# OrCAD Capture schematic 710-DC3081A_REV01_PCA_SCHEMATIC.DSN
size Custom; rev: 01; note: DEMO CIRCUIT 3081A; note: SINGLE SWITCH TRANSMITTER FOR LTC4126
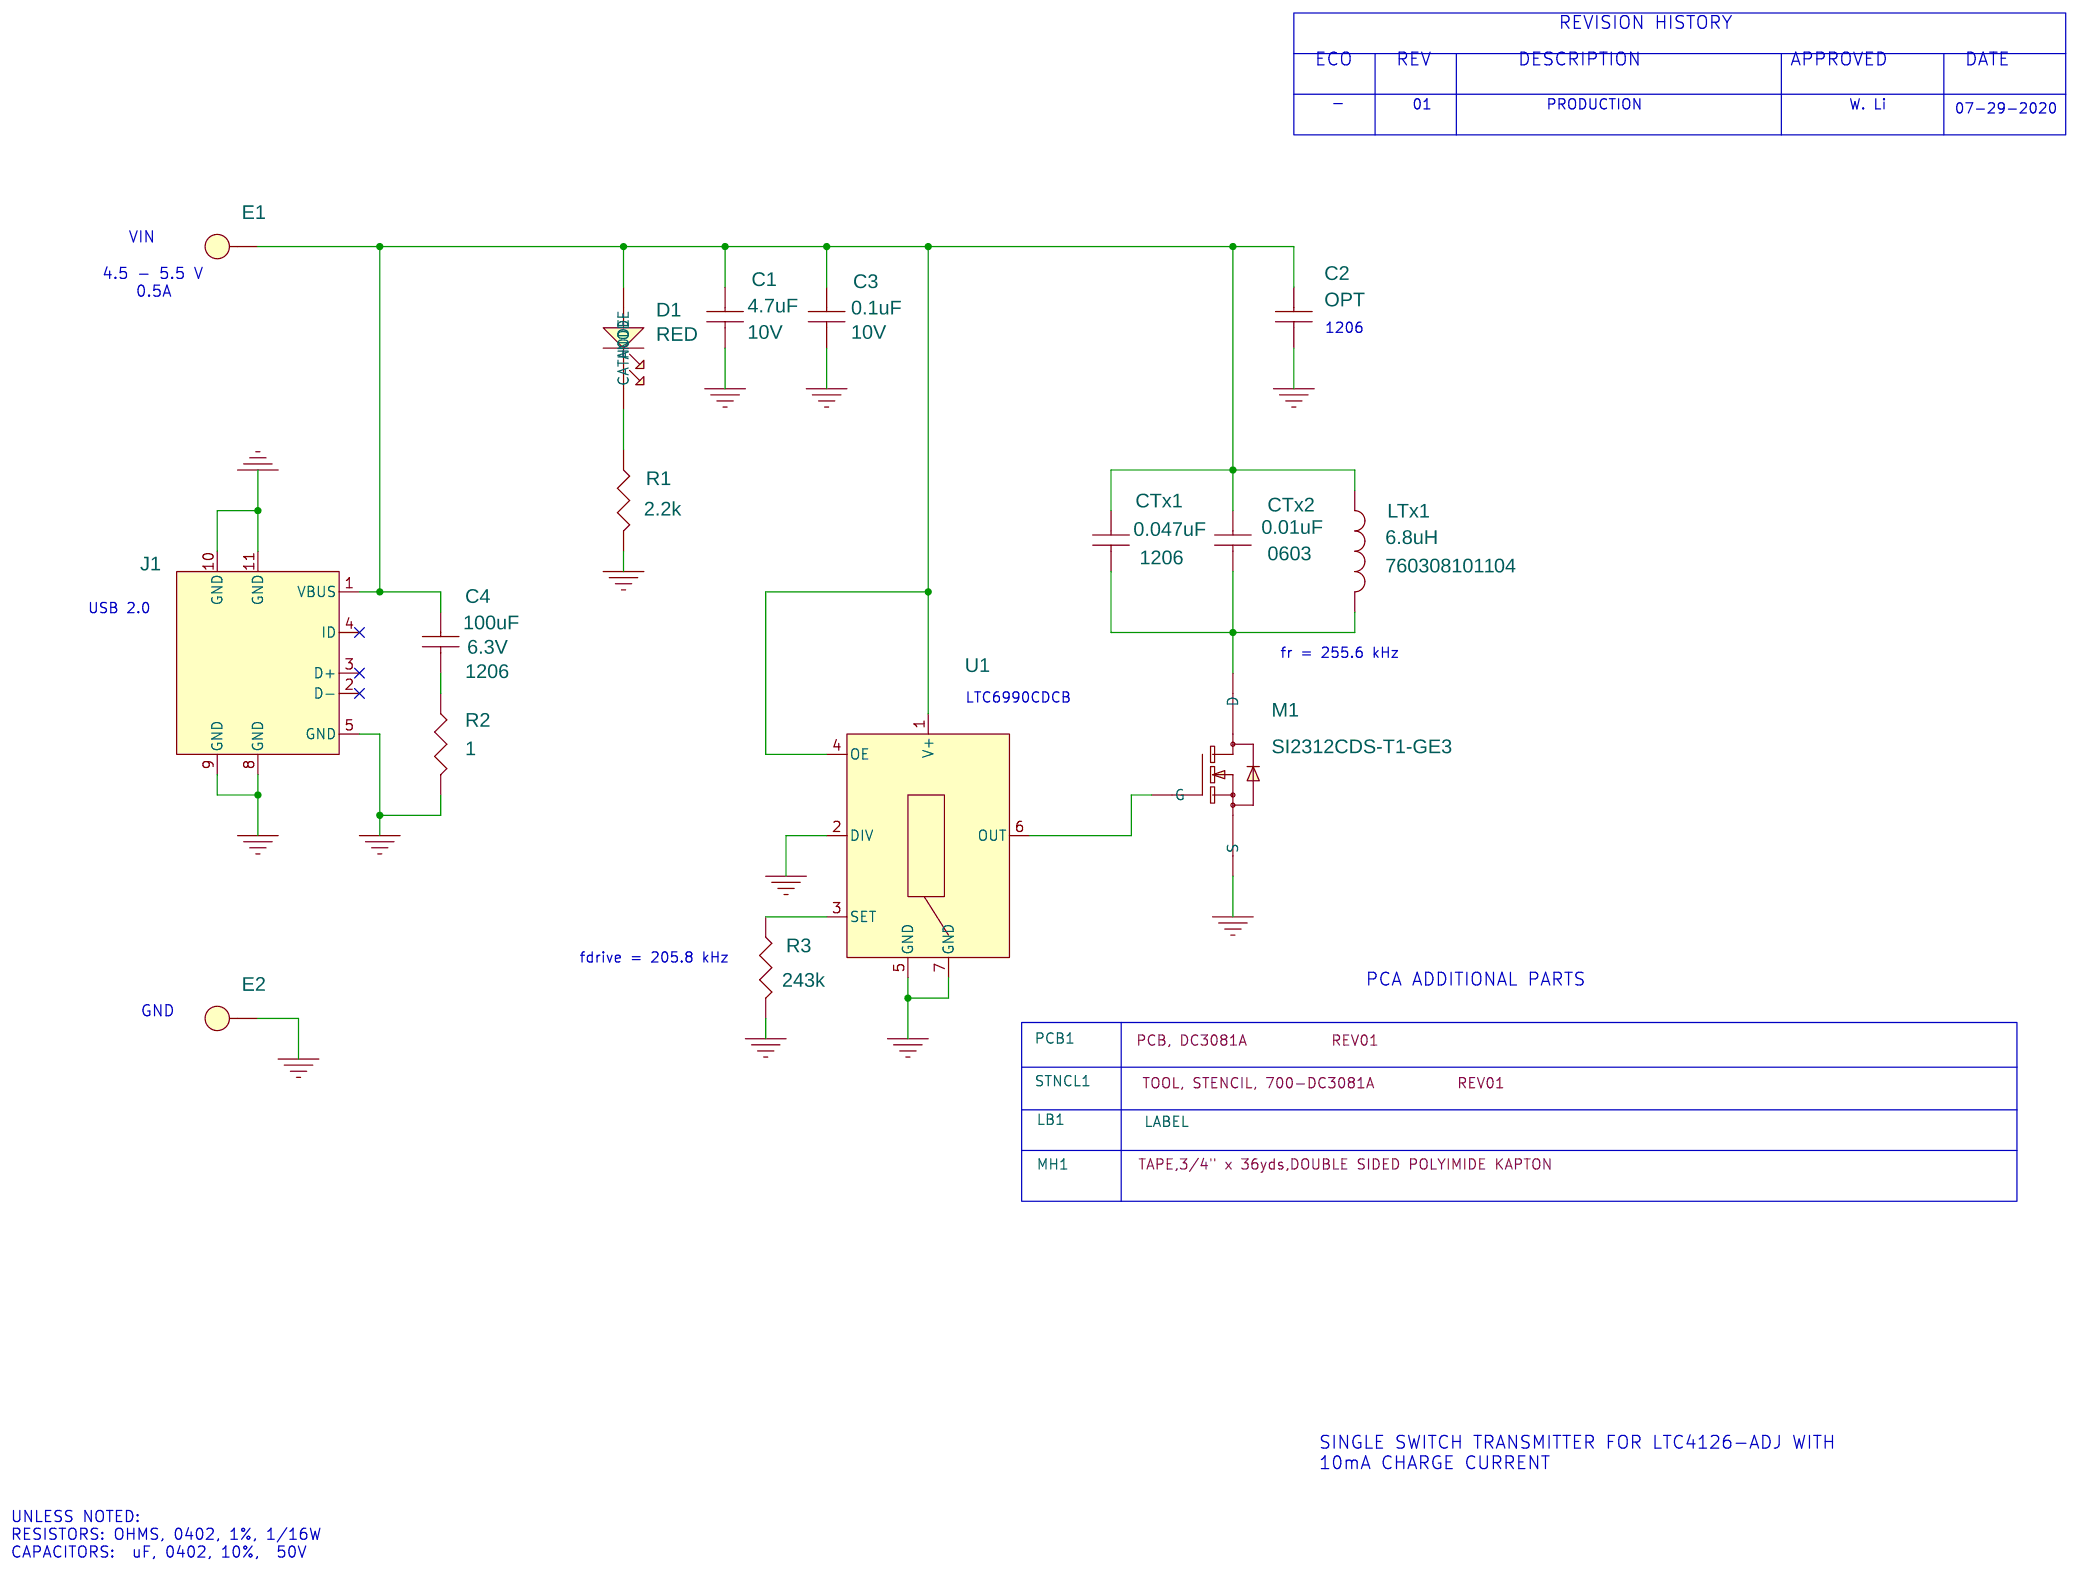
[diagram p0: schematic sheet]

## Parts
C1  4.7uF  [CC0402M]
C2  OPT  [CC1206M]
C3  0.1uF  [CC0402M]
C4  100uF  [CC1206M]
CTx1  0.047uF  [CC1206N]
CTx2  0.01uF  [CC0603N]
D1  RED  [LED_0603]
E1  TEST POINT  [MILLMAX2308]
E2  TEST POINT  [MILLMAX2308]
J1  uUSB 2.0  [TE-1932788-1]
LB1  LABEL  [895-0154_REV01]
LTx1  6.8uH  [WURTH-760308101104]
M1  SI2312CDS-T1-GE3  [SOT23-3N]
MH1  TAPE  [UNASSIGNED]
PCB1  PCB, DC3081A
R1  2.2k  [CR0402M]
R2  1  [CR0402M]
R3  243k  [CR0402M]
STNCL1  TOOL, STENCIL, 700-DC3081A
U1  OSCILLATOR,TimerBlox: VCO  [LTC-DCB-6-1715]

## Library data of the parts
C1 = CAP: CAP.,4.7uF,X5R,10V,10%,0402; CLASS: DISCRETE; Dielectric Type: X5R; FPLIST: CC0402N,CC0402L,CC0402M; Inventory Qty: 30305; Manufacturer: TDK; Manufacturer PN: C1005X5R1A475K050BC; PART_NUMBER: 150-2275; Package Size: 0402; Rated Voltage: 10V; Tolerance: 10%
C2 = CAP: CAP., OPTION, 1206; CLASS: DISCRETE; FPLIST: CC1206N,CC1206L,CC1206M; PART_NUMBER: 150-3160; Package Size: 1206; Package Type: SMD
C3 = CAP: CAP.,0.1uF,X5R,10V,10%,0402; CLASS: DISCRETE; Dielectric Type: X5R; FPLIST: CC0402N,CC0402L,CC0402M; Inventory Qty: 52369; Manufacturer: AVX; Manufacturer PN: 0402ZD104KAT2A; PART_NUMBER: 150-3293; Package Size: 0402; Rated Voltage: 10V; Tolerance: 10%
C4 = CAP: CAP.,100uF,X5R,6.3V,20%,1206; CLASS: DISCRETE; Dielectric Type: X5R; FPLIST: CC1206N,CC1206L,CC1206M; Inventory Qty: 10031; Manufacturer: MURATA; Manufacturer PN: GRM31CR60J107ME39L; PART_NUMBER: 150-0261; Package Size: 1206; Package Type: SMD; Rated Voltage: 6.3V; Tolerance: 20%
CTx1 = CAP: CAP.,0.047uF,C0G,50V,5%,1206; CLASS: DISCRETE; Dielectric Type: C0G; FPLIST: CC1206N,CC1206L,CC1206M; Inventory Qty: 5134; Manufacturer: MURATA; Manufacturer PN: GCM31M5C1H473JA16L; PART_NUMBER: 150-0469; Package Size: 1206; Package Type: Surface Mount, MLCC; Rated Voltage: 50V; Temperature Coefficient: C0G, NP0; Tolerance: 5%
CTx2 = CAP: CAP.,0.01uF,C0G,25V,5%,0603; CLASS: DISCRETE; Dielectric Type: C0G; FPLIST: CC0603N,CC0603L,CC0603M; Inventory Qty: 18308; Manufacturer: KEMET; Manufacturer PN: C0603C103J3GACTU; PART_NUMBER: 150-2101; Package Size: 0603; Package Type: SMD; Rated Voltage: 25V; Tolerance: 5%
D1 = LED: LED,RED,WATER-CLEAR,0603; CLASS: DISCRETE; FPLIST: LED_0603,LED-LTST-C193KRKT-5A; Inventory Qty: 15266; Manufacturer: LITE-ON; Manufacturer PN: LTST-C193KRKT-5A; PART_NUMBER: 270-0070; Package Size: 0603 (1608 Metric); Package Type: 0603
E1 E2 = TEST_POINT_.156_MILL-MAX_2308: TEST POINT,TURRET,0.064" MTG. HOLE,PCB 0.062" THK; CLASS: IO; Inventory Qty: 917580; Manufacturer: MILL-MAX; Manufacturer PN: 2308-2-00-80-00-00-07-0; PART_NUMBER: 260-0004
J1 = MICRO_USB_2.0: CONN.,uUSB 2.0,RCPT.,5-PIN,1PORT,REVERSE MOUNT,R/A HORZ.,TYPE B, FLANGELESS; CLASS: IO; Inventory Qty: 3757; Manufacturer: TE CONNECTIVITY; Manufacturer PN: 1932788-1; PART_NUMBER: 250-0536
LB1 = BLANK_LABEL: LABEL SPEC, DEMO BOARD SERIAL NUMBER; Inventory Qty: 0; Manufacturer: BRADY; Manufacturer PN: THT-96-717-10; PART_NUMBER: 895-0154
LTx1 = IND_ALT: IND.,6.8uH,WIRELESS CHRG. COIL TX.,10%,2.5A,125mOHMS,20.5mm Dia x 2.6mm H,1 COIL,1 LAYER; CLASS: DISCRETE; Inventory Qty: 342; Manufacturer: WURTH ELEKTRONIK; Manufacturer PN: 760308101104; PART_NUMBER: 200-0704; Package Size: 20.5mm Dia x 2.6mm H; Tolerance: 10%
M1 = SI2312CDS-T1-GE3: XSTR.,MOSFET, N-CH,20V,6A,SOT23-3; CLASS: DISCRETE; Inventory Qty: 457; Manufacturer: VISHAY; Manufacturer PN: Si2312CDS-T1-GE3; PART_NUMBER: 240-0122; Package Size: SOT-23-3; Package Type: SOT23-3; Polarity: N-Channel; Rated Voltage: 20V
MH1 = BLANK_MECHANICAL_PART: TAPE,3/4" x 36yds,DOUBLE SIDED POLYIMIDE KAPTON; CLASS: DISCRETE; Inventory Qty: 28303; Manufacturer: BERTECH; Manufacturer PN: PPTDE-3/4; PART_NUMBER: 450-0007
PCB1 = BLANK_PCB_PART: BOM Notes: REV01; CLASS: DISCRETE; Inventory Qty: 0; Manufacturer: ADI APPROVED SUPPLIER; Manufacturer PN: 600-DC3081A; PART_NUMBER: 600-DC3081A
R1 = RES: RES.,2.2k OHMS,5%,1/16W,0402,AEC-Q200; CLASS: DISCRETE; Inventory Qty: 57011; Manufacturer: VISHAY; Manufacturer PN: CRCW04022K20JNED; PART_NUMBER: 100-0324; Package Size: 0402; Rated Power: 1/16W; Temperature Coefficient: 200ppm; Tolerance: 5%
R2 = RES: RES.,1 OHM,1%,1/16W,0402,AEC-Q200; CLASS: DISCRETE; FPLIST: CR0402N,CR0402L,CR0402M; Inventory Qty: 54224; Manufacturer: VISHAY; Manufacturer PN: CRCW04021R00FKED; PART_NUMBER: 100-0241; Package Size: 0402; Rated Power: 1/16W; Temperature Coefficient: +/-100ppm; Tolerance: 1%
R3 = RES: RES.,243k OHMS,1%,1/16W,0402,AEC-Q200; CLASS: DISCRETE; FPLIST: CR0402L,CR0402N,CR0402M; Inventory Qty: 39650; Manufacturer: NIC; Manufacturer PN: NRC04F2433TRF; PART_NUMBER: 100-1321; Package Size: 0402; Rated Power: 1/16W; Temperature Coefficient: +/-100ppm; Tolerance: 1%
STNCL1 = BLANK_STENCIL_PART: BOM Notes: REV01; CLASS: DISCRETE; Inventory Qty: 0; Manufacturer: ANALOG DEVICES; Manufacturer PN: 830-DC3081A; PART_NUMBER: 830-DC3081A
U1 = LTC6990-DCB: OSCILLATOR,TimerBlox: VCO,5pF,90ppm,DFN-5; CLASS: DISCRETE; Frequency Stability: 90ppm; Inventory Qty: 140; Manufacturer: ANALOG DEVICES; Manufacturer PN: LTC6990CDCB#PBF; PART_NUMBER: LTC6990CDCB#PBF

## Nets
GND: C1.2 C2.2 C3.2 E2.1(A) J1.5(GND) J1.8(GND) J1.9(GND) J1.10(GND) J1.11(GND) M1.2(S) R1.2 R2.2 R3.2 U1.2(DIV) U1.5(GND) U1.7(GND)
N12951: C1.1 C2.1 C3.1 C4.1 CTx1.1 CTx2.1 D1.2(ANODE) E1.1(A) J1.1(VBUS) LTx1.2 U1.1(V+) U1.4(OE)
N13037: R3.1 U1.3(SET)
N13053: M1.1(G) U1.6(OUT)
N13103: CTx1.2 CTx2.2 LTx1.1 M1.3(D)
N16786871: D1.1(CATHODE) R1.1
N16793883: C4.2 R2.1

Not connected (* = marked no-connect by the designer): J1 2(D-)* 3(D+)* 4(ID)*

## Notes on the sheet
- REVISION HISTORY
- ECO
- REV
- DESCRIPTION
- APPROVED
- DATE
- -
- 01
- PRODUCTION
- W. Li
- 07-29-2020
- VIN
- 4.5 - 5.5 V
      0.5A
- 1206
- USB 2.0
- fr = 255.6 kHz
- LTC6990CDCB
- fdrive = 205.8 kHz
- PCA ADDITIONAL PARTS
- GND
- SINGLE SWITCH TRANSMITTER FOR LTC4126-ADJ WITH
  10mA CHARGE CURRENT
- UNLESS NOTED:
  RESISTORS: OHMS, 0402, 1%, 1/16W
  CAPACITORS:  uF, 0402, 10%,  50V
